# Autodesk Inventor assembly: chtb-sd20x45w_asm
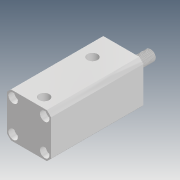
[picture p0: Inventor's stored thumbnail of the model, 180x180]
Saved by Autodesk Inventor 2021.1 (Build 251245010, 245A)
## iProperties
Company: Microsoft
Created: 2018-05
Part Number: chtb-sd20x45w_asm
Description: STEP AP214
Document SubType Name: Assembly
Designer: user
Title: chtb-sd20x45w_asm.STEP
Author: Windows
Revision Number: ÈÎºÎ
Sending System: SolidWorks 2015
Preprocessor: SwSTEP 2.0
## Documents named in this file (4)
- D:\Vault_2016\Projekty\Clamptek\Hydraulic\CHTB\CHTB-20\Inventor\CHTB-SD20x45W\chtb-sd20x45w_asm.iam
- D:\Vault_2016\Projekty\Clamptek\Hydraulic\CHTB\CHTB-20\Inventor\CHTB-SD20x45W\CHTB-SD20X45NBT.ipt
- D:\Vault_2016\Projekty\Clamptek\Hydraulic\CHTB\CHTB-20\Inventor\CHTB-SD20x45W\CHTB-SD20X45WHSG.ipt
- D:\Vault_2016\Projekty\Clamptek\Hydraulic\CHTB\CHTB-20\Inventor\CHTB-SD20x45W\QG.ipt
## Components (3 placed, 3 different names)
1. CHTB-SD20X45NBT_1
2. CHTB-SD20X45WHSG_2
3. QG_3
